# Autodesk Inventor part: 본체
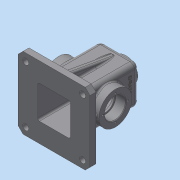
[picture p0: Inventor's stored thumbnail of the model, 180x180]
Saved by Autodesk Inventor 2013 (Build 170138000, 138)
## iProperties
Created: 2018-10
Part Number: 본체
Material: 일반
Document SubType Name: Modeling
Designer: Administrator
Density: 1 g/cm^3
Author: Administrator
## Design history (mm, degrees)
sketch "스케치1"
  geometry: L1 (-32.5, -32.5)-(32.5, -32.5); L2 (32.5, -32.5)-(32.5, 32.5); L3 (32.5, 32.5)-(-32.5, 32.5); L4 (-32.5, 32.5)-(-32.5, -32.5); L5 (-32.5, -32.5)-(32.5, 32.5); L6 (32.5, -32.5)-(-32.5, 32.5); 1 further point
  constraints: 12 end point, 2 midpoint, 2 parallel, 1 horizontal, 1 perpendicular
  dimensions: "d0" = 65 distance of L3.end L2.end; "d1" = 65 distance of L2.end L1.end
extrude "돌출1" new body sketch "스케치1" stored distance "d2" = 110; taper "d3" = 0 deg
fillet "모깎기1" dims "d4" = 8
fillet "모깎기2" dims "d5" = 8
feature "쉘1" dims "d12" = 5
sketch "스케치4"
  geometry: C1 r 27.5 at (24.5, 55); 1 further point
  constraints: 1 centre point, 1 coincident
  dimensions: "d13" = 55 diameter of C1
extrude "돌출4" join sketch "스케치4" distance "d14" = 15; taper "d15" = 0 deg
sketch "스케치5"
  geometry: C1 r 27.5 at (24.5, 55); 1 further point
  constraints: 1 centre point, 1 coincident
  dimensions: "d16" = 55 diameter of C1
extrude "돌출5" join sketch "스케치5" distance "d17" = 15; taper "d18" = 0 deg
node "작업 평면1"
sketch "스케치10"
  geometry: C1 r 20 at (0, 0); 1 further point
  constraints: 1 centre point, 1 coincident
  dimensions: "d33" = 40 diameter of C1
extrude "돌출9" join sketch "스케치10" distance "d34" = 10; taper "d35" = 7 deg
hole "구멍1" diameter "d38" = 22.835; stored, may be unused: countersink angle "d42" = 90 deg, drill point angle "d44" = 118 deg; dims "d36" = 10, "d37" = 10, "d39" = 30, "d40" = 4, "d41" = 2, "d43" = 30
fillet "모깎기3" dims "d45" = 3
sketch "스케치11"
  geometry: C1 r 27.5 at (0, 0) reference; C2 r 17.5 at (0, 0)
  constraints: 1 centre point, 1 coincident
  dimensions: "d46" = 35 diameter of C2
extrude "돌출10" cut sketch "스케치11" distance "d47" = 17; taper "d48" = 0 deg
sketch "스케치12"
  geometry: C1 r 17.5 at (0, 0) reference; C2 r 15 at (0, 0)
  constraints: 1 centre point, 1 coincident
  dimensions: "d49" = 30 diameter of C2
extrude "돌출11" cut sketch "스케치12" distance "d50" = 3; taper "d51" = 0 deg
sketch "스케치13"
  geometry: C1 r 27.5 at (0, 0) reference; C2 r 17.5 at (0, 0)
  constraints: 1 centre point, 1 coincident
  dimensions: "d52" = 35 diameter of C2
extrude "돌출12" cut sketch "스케치13" distance "d53" = 17; taper "d54" = 0 deg
sketch "스케치14"
  geometry: C1 r 17.5 at (0, 0) reference; C2 r 15 at (0, 0)
  constraints: 1 centre point, 1 coincident
  dimensions: "d55" = 30 diameter of C2
extrude "돌출13" cut sketch "스케치14" distance "d56" = 3; taper "d57" = 0 deg
fillet "모깎기4" dims "d58" = 3
sketch "스케치15"
  geometry: L1 (24.5, 32.5)-(-24.5, 32.5) reference; L2 (-32.5, 24.5)-(-32.5, -24.5) reference; L3 (-24.5, -32.5)-(24.5, -32.5) reference; L4 (32.5, -24.5)-(32.5, 24.5) reference; L5 (-60, -60)-(60, -60); L6 (60, -60)-(60, 60); L7 (60, 60)-(-60, 60); L8 (-60, 60)-(-60, -60); L9 (-60, -60)-(60, 60); L10 (60, -60)-(-60, 60); L11 (27.5, 24.5)-(27.5, -24.5); L12 (24.5, -27.5)-(-24.5, -27.5); L13 (-27.5, -24.5)-(-27.5, 24.5); L14 (-24.5, 27.5)-(24.5, 27.5); A1 r 8 centre (24.5, 24.5) between (32.5, 24.5) and (24.5, 32.5) reference; A2 r 8 centre (-24.5, 24.5) between (-24.5, 32.5) and (-32.5, 24.5) reference; A3 r 8 centre (-24.5, -24.5) between (-32.5, -24.5) and (-24.5, -32.5) reference; A4 r 8 centre (24.5, -24.5) between (24.5, -32.5) and (32.5, -24.5) reference; A5 r 3 centre (24.5, 24.5) between (27.5, 24.5) and (24.5, 27.5); A6 r 3 centre (24.5, -24.5) between (24.5, -27.5) and (27.5, -24.5); A7 r 3 centre (-24.5, -24.5) between (-27.5, -24.5) and (-24.5, -27.5); A8 r 3 centre (-24.5, 24.5) between (-24.5, 27.5) and (-27.5, 24.5); 3 further points
  constraints: 20 end point, 8 point on circle, 4 centre point, 3 midpoint, 2 parallel, 1 coincident, 1 horizontal, 1 perpendicular, 7 other
  dimensions: "d59" = 120 distance of L7.end L6.end; "d60" = 120 distance of L6.end L5.end; "d61" = 5 distance between parallel lines of L4 L11
extrude "돌출14" join sketch "스케치15" distance "d62" = 10; taper "d63" = 0 deg
chamfer "모따기2" distance "d64" = 8; stored, may be unused: second distance "d65" = 2, angle "d66" = 45 deg
sketch "스케치16"
  geometry: C1 r 5 at (47.5, -47.5); C2 r 5 at (47.5, 47.5); C3 r 5 at (-47.5, -47.5); C4 r 5 at (-47.5, 47.5); 1 further point
  constraints: 4 centre point
  dimensions: "d67" = 10 diameter of C1; "d68" = 10 diameter of C2; "d69" = 47.5 horizontal distance of C1.centre point (0, 0); "d70" = 47.5 horizontal distance of C1.centre point (0, 0); "d71" = 47.5 horizontal distance of point (0, 0) C2.centre; "d72" = 47.5 horizontal distance of point (0, 0) C2.centre; "d73" = 10 diameter of C3; "d74" = 10 diameter of C4; "d75" = 47.5 horizontal distance of C4.centre point (0, 0); "d76" = 47.5 horizontal distance of C4.centre point (0, 0); "d77" = 47.5 horizontal distance of C3.centre point (0, 0); "d78" = 47.5 horizontal distance of C3.centre point (0, 0)
extrude "돌출15" cut sketch "스케치16" stored distance "d79" = 10; taper "d80" = 0 deg
sketch "스케치17"
  geometry: L1 (42.5, -27.5)-(42.5, -45); L2 (30.5, -17.5)-(47.5, -17.5) reference; L3 (47.5, -17.5)-(47.5, -27.5) reference; L4 (47.5, -27.5)-(35.5, -27.5) reference; L5 (32.5, -30.5)-(32.5, -45) reference; L6 (32.5, -45)-(60, -45) reference; L7 (60, -45)-(60, -55) reference; L8 (60, -55)-(27.5, -55) reference; L9 (27.5, -55)-(27.5, -15) reference; L10 (27.5, -15)-(30.5, -15) reference; L11 (30.5, -15)-(30.5, -17.5) reference; L12 (-47.5, -17.5)-(-30.5, -17.5) reference; L13 (-30.5, -17.5)-(-30.5, -15) reference; L14 (-30.5, -15)-(-27.5, -15) reference; L15 (-27.5, -15)-(-27.5, -55) reference; L16 (-27.5, -55)-(-60, -55) reference; L17 (-60, -55)-(-60, -45) reference; L18 (-60, -45)-(-32.5, -45) reference; L19 (-32.5, -45)-(-32.5, -30.5) reference; L20 (-35.5, -27.5)-(-47.5, -27.5) reference; L21 (-47.5, -27.5)-(-47.5, -17.5) reference; L22 (-27.5, 47)-(-27.5, 15) reference; L23 (-27.5, 15)-(-30.5, 15) reference; L24 (-30.5, 15)-(-30.5, 17.5) reference; L25 (-30.5, 17.5)-(-47.5, 17.5) reference; L26 (-47.5, 17.5)-(-47.5, 27.5) reference; L27 (-47.5, 27.5)-(-35.5, 27.5) reference; L28 (-32.5, 30.5)-(-32.5, 47) reference; L29 (-24.5, 55)-(-23.882, 55) reference; L30 (-20.904, 57.634)-(-20, 65) reference; L31 (-20, 65)-(-11.418, 65) reference; L32 (-11.418, 65)-(-11.418, 50) reference; L33 (-11.418, 50)-(-24.5, 50) reference; L34 (24.5, 50)-(11.418, 50) reference; L35 (11.418, 50)-(11.418, 65) reference; L36 (11.418, 65)-(20, 65) reference; L37 (20, 65)-(20.904, 57.634) reference; L38 (23.882, 55)-(24.5, 55) reference; L39 (32.5, 47)-(32.5, 30.5) reference; L40 (35.5, 27.5)-(47.5, 27.5) reference; L41 (47.5, 27.5)-(47.5, 17.5) reference; L42 (47.5, 17.5)-(30.5, 17.5) reference; L43 (30.5, 17.5)-(30.5, 15) reference; L44 (30.5, 15)-(27.5, 15) reference; L45 (27.5, 15)-(27.5, 47) reference; A1 r 3 centre (35.5, -30.5) between (35.5, -27.5) and (32.5, -30.5) reference; A2 r 3 centre (-35.5, -30.5) between (-32.5, -30.5) and (-35.5, -27.5) reference; A3 r 3 centre (-24.5, 47) between (-24.5, 50) and (-27.5, 47) reference; A4 r 3 centre (-35.5, 30.5) between (-35.5, 27.5) and (-32.5, 30.5) reference; A5 r 8 centre (-24.5, 47) between (-24.5, 55) and (-32.5, 47) reference; A6 r 3 centre (-23.882, 58) between (-23.882, 55) and (-20.904, 57.634) reference; A7 r 3 centre (24.5, 47) between (27.5, 47) and (24.5, 50) reference; A8 r 3 centre (23.882, 58) between (20.904, 57.634) and (23.882, 55) reference; A9 r 8 centre (24.5, 47) between (32.5, 47) and (24.5, 55) reference; A10 r 3 centre (35.5, 30.5) between (32.5, 30.5) and (35.5, 27.5) reference; 1 further point
  constraints: 2 end point, 2 point on line, 1 vertical
  dimensions: "d81" = 15 distance between parallel lines of L1 L9
feature "리브1" sketch "스케치17" dims "d83" = 1, "d84" = 6, "d85" = 0, "d86" = 0, "d87" = 1, "d88" = 1
sketch "스케치18"
  geometry: L1 (-2.933, -40.582)-(-45, -48); L2 (47, 27.5)-(-55, 27.5) reference; L3 (-55, 27.5)-(-55, 60) reference; L4 (-55, 60)-(-45, 60) reference; L5 (-45, 60)-(-45, 32.5) reference; L6 (-45, 32.5)-(47, 32.5) reference; L7 (55, 24.5)-(55, 23.882) reference; L8 (57.634, 20.904)-(65, 20) reference; L9 (65, 20)-(65, 11.418) reference; L10 (65, 11.418)-(50, 11.418) reference; L11 (50, 11.418)-(50, 24.5) reference; L12 (50, -24.5)-(50, -11.418) reference; L13 (50, -11.418)-(65, -11.418) reference; L14 (65, -11.418)-(65, -20) reference; L15 (65, -20)-(57.634, -20.904) reference; L16 (55, -23.882)-(55, -24.5) reference; L17 (47, -32.5)-(-45, -32.5) reference; L18 (-45, -32.5)-(-45, -60) reference; L19 (-45, -60)-(-55, -60) reference; L20 (-55, -60)-(-55, -27.5) reference; L21 (-55, -27.5)-(47, -27.5) reference; A1 r 3 centre (47, 24.5) between (50, 24.5) and (47, 27.5) reference; A2 r 8 centre (47, 24.5) between (55, 24.5) and (47, 32.5) reference; A3 r 3 centre (58, 23.882) between (55, 23.882) and (57.634, 20.904) reference; A4 r 3 centre (47, -24.5) between (47, -27.5) and (50, -24.5) reference; A5 r 3 centre (58, -23.882) between (57.634, -20.904) and (55, -23.882) reference; A6 r 8 centre (47, -24.5) between (47, -32.5) and (55, -24.5) reference; 1 further point
  constraints: 2 end point, 1 point on line
  dimensions: "d89" = 12 distance from line of L19 L1.end; "d90" = 10 deg angle of L19 L1
feature "리브2" sketch "스케치18" dims "d91" = 1, "d92" = 10, "d93" = 0, "d94" = 0, "d95" = 1, "d96" = 1
fillet "모깎기5" dims "d97" = 3
fillet "모깎기6" dims "d98" = 3
chamfer "모따기3" distance "d99" = 1; stored, may be unused: second distance "d100" = 2, angle "d101" = 45 deg
fillet "모깎기7" dims "d102" = 0.3
sketch "스케치19"
  geometry: L1 (0, 0)-(0, 21); C1 r 27.5 at (0, 0) reference; 1 further point
  constraints: 2 coincident, 2 end point, 1 vertical
  dimensions: "d103" = 21 distance of L1.start L1.end
hole "구멍2" sketch "스케치19" at (0, 21) diameter "d104" = 3.242; stored, may be unused: countersink angle "d108" = 90 deg, drill point angle "d110" = 118 deg; dims "d105" = 8, "d106" = 4, "d107" = 2, "d109" = 10
sketch "스케치20"
  geometry: L1 (-8, 0)-(-8, -92) reference; L2 (4.5, 18)-(44.5, 18) reference; 1 further point
  constraints: 1 other
  dimensions: "d114" = 32.5 distance from line of point (24.5, -8) L1; "d115" = 26 distance from line of point (24.5, -8) L2
feature "엠보싱1" sketch "스케치20" dims "d116" = 0.5, "d117" = 0
fillet "모깎기8" dims "d118" = 3
fillet "모깎기9" dims "d119" = 3
fillet "모깎기10" dims "d120" = 1
chamfer "모따기4" distance "d121" = 1; stored, may be unused: second distance "d122" = 2, angle "d123" = 45 deg
node "솔리드1"
mirror "대칭1"
mirror "대칭2"
pattern_circular "원형 패턴1" dims angle "d112" = 360 deg
mirror "대칭3"
node "절단 모서리 투영1"
node "절단 모서리 투영2"
other parameters: "d32" = 65
